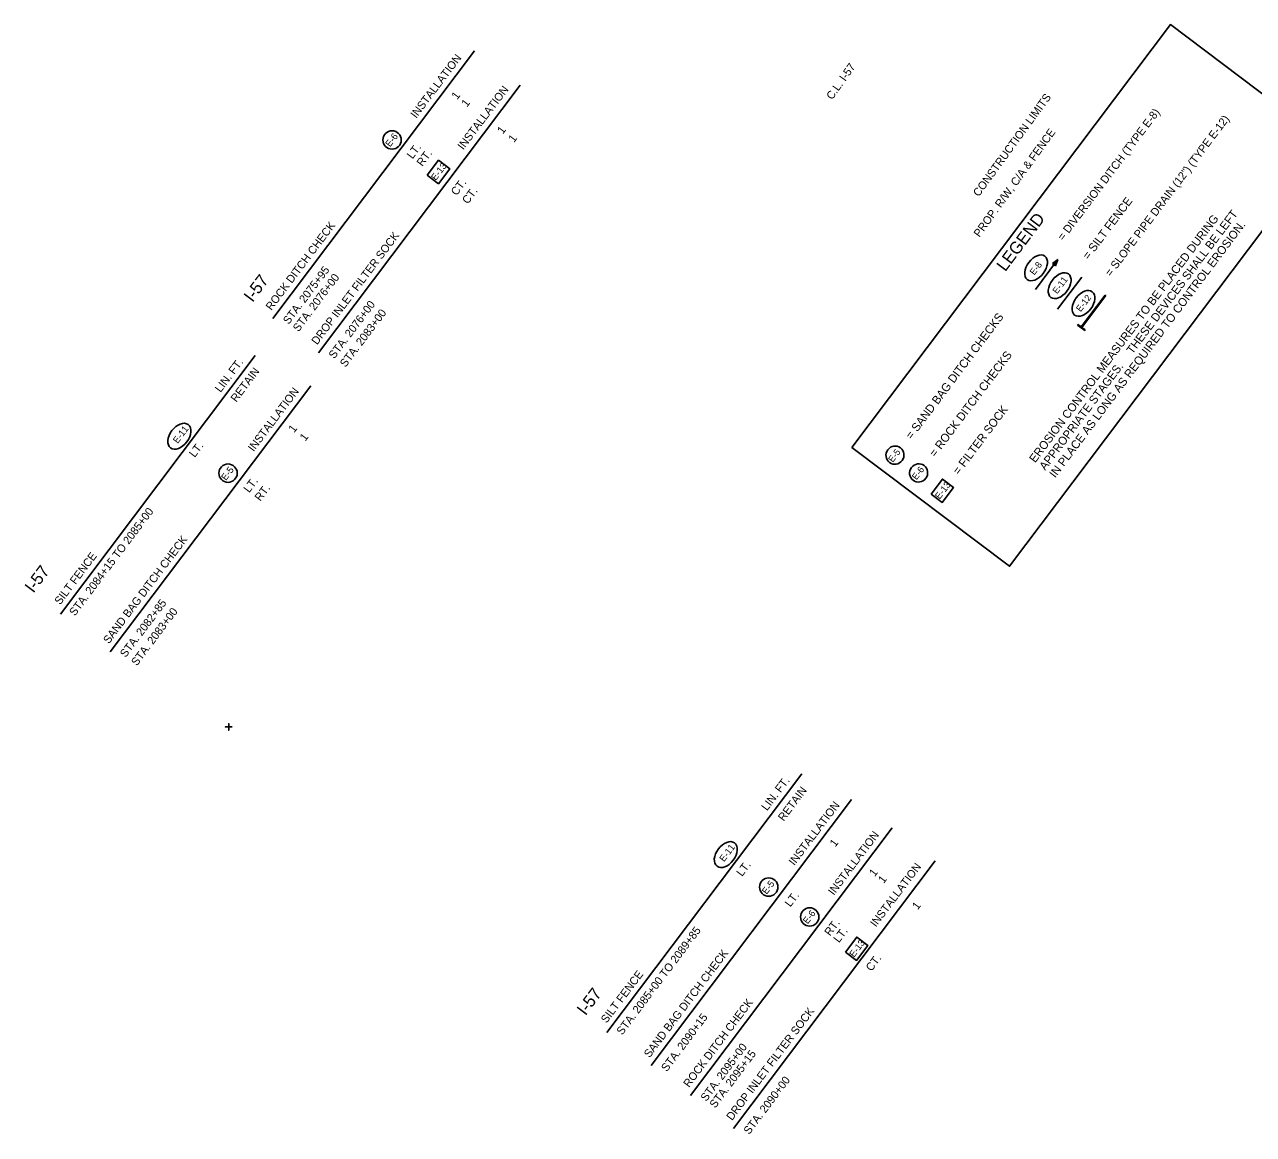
# Model space of a CAD drawing. Extents: x 1713742 to 1715480, y 763715 to 765350.
# Drawn here: x 1713742 to 1714663, y 763715 to 764547 of the extents above; entities that cross this region are included whole.
import ezdxf

# ---------------------------------------------------------------- set-up
doc = ezdxf.new("R2010")
doc.units = 0
for name, color, linetype in [('1', 7, 'Continuous'), ('44', 7, 'Continuous'), ('Level 1', 7, 'Continuous'), ('Level 44', 7, 'Continuous'), ('Plan Notes', 7, 'Continuous'), ('R_Draft', 7, 'Continuous')]:
    doc.layers.add(name, color=color, linetype=linetype)

msp = doc.modelspace()

# ---------------------------------------------------------------- linework, layer by layer
at = {"layer": '1'}
for points in [[(1714362.47, 764230.05), (1714601.19, 764546.83), (1714719.3, 764457.83), (1714480.58, 764141.04)], [(1714044.19, 764433.96), (1714052.63, 764445.16), (1714061.02, 764438.84), (1714052.58, 764427.64)], [(1714421.82, 764195.09), (1714430.26, 764206.3), (1714438.65, 764199.97), (1714430.21, 764188.77)], [(1714357.63, 763851.95), (1714366.07, 763863.15), (1714374.46, 763856.83), (1714366.02, 763845.63)]]:
    msp.add_lwpolyline(points, close=True, dxfattribs=at)
for centre in [(1714017.86, 764460.38), (1713894.88, 764210.74), (1714300.12, 763900.64), (1714330.82, 763878.22)]:
    msp.add_circle(centre, 6.88, dxfattribs=at)
for centre in [(1713858.43, 764238.38), (1714267.94, 763924.95)]:
    msp.add_ellipse(centre, major_axis=(6.59, 8.75), ratio=0.638788, dxfattribs=at)
at = {"layer": '44'}
for p, q in [((1713928.48, 764326.74), (1714079.55, 764527.21)), ((1713962.71, 764300.95), (1714113.78, 764501.42)), ((1713769.39, 764105.14), (1713915.33, 764298.81)), ((1713806.66, 764076.94), (1713956.83, 764276.22)), ((1714178.9, 763791.7), (1714324.84, 763985.37)), ((1714211.89, 763766.84), (1714362.06, 763966.12)), ((1714241.44, 763744.58), (1714392.51, 763945.05)), ((1714273.67, 763719.78), (1714424.74, 763920.25))]:
    msp.add_line(p, q, dxfattribs=at)
at = {"layer": 'Level 1'}
for p, q in [((1714516.89, 764370.87), (1714512.85, 764367.9)), ((1714512.85, 764367.9), (1714515.16, 764366.16)), ((1714515.92, 764370.04), (1714513.15, 764367.69)), ((1714515.98, 764369.98), (1714513.44, 764367.47)), ((1714516.05, 764369.91), (1714513.72, 764367.26)), ((1714514.3, 764366.81), (1714516.21, 764369.8)), ((1714514.58, 764366.6), (1714516.28, 764369.74)), ((1714514.87, 764366.38), (1714516.37, 764369.71)), ((1714515.16, 764366.16), (1714516.89, 764370.87))]:
    msp.add_line(p, q, dxfattribs=at)
msp.add_lwpolyline([(1714499.93, 764348.36), (1714515.88, 764369.52)], dxfattribs=at)
for centre, major_axis, ratio in [((1714500.46, 764364.55), (6.59, 8.75), 0.622952), ((1714518.18, 764351.22), (6.59, 8.76), 0.622952), ((1714535.99, 764337.97), (6.59, 8.75), 0.622952), ((1714394.73, 764224.24), (-4.14, -5.5), 0.97521), ((1714412.45, 764210.91), (-4.14, -5.5), 0.97521)]:
    msp.add_ellipse(centre, major_axis=major_axis, ratio=ratio, dxfattribs=at)
at = {"layer": 'Level 44'}
for p, q in [((1714552.3, 764344.13), (1714534.33, 764320.27)), ((1714552.7, 764343.83), (1714534.73, 764319.97)), ((1714552.3, 764344.13), (1714552.7, 764343.83)), ((1714531.54, 764321.74), (1714531.84, 764322.14)), ((1714536.91, 764317.7), (1714531.54, 764321.74)), ((1714534.33, 764320.27), (1714531.84, 764322.14)), ((1714537.21, 764318.1), (1714534.73, 764319.97)), ((1714536.91, 764317.7), (1714537.21, 764318.1))]:
    msp.add_line(p, q, dxfattribs=at)
msp.add_lwpolyline([(1714516.58, 764333.58), (1714534.68, 764357.66)], dxfattribs=at)
at = {"layer": 'Plan Notes'}
msp.add_lwpolyline([(1713895.44, 764020.61), (1713895.44, 764023.11), (1713895.44, 764020.61), (1713892.94, 764020.61), (1713895.44, 764020.61), (1713895.44, 764018.11), (1713895.44, 764020.61), (1713897.94, 764020.61)], dxfattribs=at)

# ---------------------------------------------------------------- texts
at = {"layer": '1'}
for s, rotation, p in [('E-6 ', 53, (1714016.34, 764454.74)), ('E-13', 52.61773, (1714050.59, 764429.64)), ('E-11', 53, (1713857.13, 764232.58)), ('E-5 ', 53, (1713893.31, 764204.87)), ('E-13', 52.61773, (1714428.22, 764190.78)), ('E-11', 53, (1714266.65, 763919.14)), ('E-5 ', 53, (1714298.54, 763894.78)), ('E-6 ', 53, (1714329.29, 763872.58)), ('E-13', 52.61773, (1714364.03, 763847.63))]:
    msp.add_text(s, height=4.999, rotation=rotation, dxfattribs=at).set_placement(p)
at = {"layer": '44'}
for s, p in [('INSTALLATION', (1714035.91, 764476.21)), ('1', (1714066.6, 764490.14)), ('INSTALLATION', (1714071.2, 764452.52)), ('1', (1714073.99, 764484.57)), ('1', (1714100.83, 764464.35)), ('LT.', (1714033.11, 764445.71)), ('1', (1714109.22, 764458.02)), ('RT.', (1714040.51, 764440.13)), ('CT.', (1714066.18, 764418.24)), ('CT.', (1714074.58, 764411.92)), ('ROCK DITCH CHECK', (1713927.4, 764332.22)), ('DROP INLET FILTER SOCK', (1713961.63, 764306.43)), ('STA. 2075+95', (1713940.33, 764321.77)), ('STA. 2075+95', (1713940.33, 764321.77)), ('STA. 2076+00', (1713947.72, 764316.2)), ('STA. 2076+00', (1713974.55, 764295.98)), ('STA. 2083+00', (1713982.95, 764289.65)), ('LIN. FT.', (1713889.31, 764270.78)), ('RETAIN', (1713901.13, 764263.49)), ('INSTALLATION', (1713914.09, 764226.41)), ('1', (1713944.43, 764240.6)), ('1', (1713944.43, 764240.6)), ('1', (1713952.83, 764234.27)), ('LT.', (1713869.93, 764222.08)), ('LT.', (1713910.73, 764195.62)), ('LT.', (1713910.73, 764195.62)), ('RT.', (1713919.12, 764189.29)), ('STA. 2084+15 TO 2085+00', (1713780.11, 764103.31)), ('SAND BAG DITCH CHECK', (1713805.58, 764082.42)), ('SILT FENCE      ', (1713769.07, 764111.63)), ('STA. 2082+85', (1713818.16, 764072.23)), ('STA. 2082+85', (1713818.16, 764072.23)), ('STA. 2083+00', (1713826.55, 764065.91)), ('LIN. FT.', (1714298.82, 763957.34)), ('RETAIN', (1714311.33, 763949.55)), ('INSTALLATION', (1714319.32, 763916.32)), ('INSTALLATION', (1714348.87, 763894.05)), ('1', (1714350.01, 763930.24)), ('1', (1714350.01, 763930.24)), ('LT.', (1714280.13, 763908.14)), ('1', (1714379.56, 763907.98)), ('INSTALLATION', (1714380.43, 763870.27)), ('1', (1714386.28, 763902.91)), ('LT.', (1714316.31, 763885.26)), ('LT.', (1714316.31, 763885.26)), ('1', (1714411.79, 763883.18)), ('STA. 2085+00 TO 2089+85', (1714190.31, 763789.36)), ('STA. 2085+00 TO 2089+85', (1714190.31, 763789.36)), ('RT.', (1714346.07, 763863.54)), ('LT.', (1714352.79, 763858.48)), ('SAND BAG DITCH CHECK', (1714210.82, 763772.33)), ('CT.', (1714377.14, 763837.08)), ('SILT FENCE      ', (1714178.58, 763798.2)), ('ROCK DITCH CHECK', (1714240.36, 763750.06)), ('STA. 2090+15', (1714223.74, 763761.88)), ('STA. 2090+15', (1714223.74, 763761.88)), ('DROP INLET FILTER SOCK', (1714272.59, 763725.27)), ('STA. 2095+00', (1714253.28, 763739.61)), ('STA. 2095+15', (1714260, 763734.55)), ('STA. 2095+15', (1714260, 763734.55)), ('STA. 2090+00', (1714285.51, 763714.82))]:
    msp.add_text(s, height=6, rotation=53, dxfattribs=at).set_placement(p)
at = {"layer": 'Level 1'}
for s, height, rotation, p in [('= DIVERSION DITCH (TYPE E-8)', 6, 53.00001, (1714520.78, 764384.46)), ('= SLOPE PIPE DRAIN (12") (TYPE E-12)', 6, 53.00001, (1714556.42, 764357.61)), ('= SILT FENCE', 6.25, 53.058, (1714539.7, 764370.22)), ('EROSION CONTROL MEASURES TO BE PLACED DURING', 6.25, 53.058, (1714499.8, 764218.1)), ('THESE DEVICES SHALL BE LEFT', 6.25, 53.058, (1714572.75, 764299.45)), ('IN PLACE AS LONG AS REQUIRED TO CONTROL EROSION.', 6.25, 53.058, (1714514.85, 764206.79)), ('E-8', 4.876, 53.00001, (1714499.15, 764358.76)), ('E-11 ', 4.876, 53.058, (1714516.25, 764344.67)), ('E-12', 4.876, 53.00001, (1714533.9, 764331.19)), ('= SAND BAG DITCH CHECKS', 6.25, 53.058, (1714407.16, 764235.57)), ('= ROCK DITCH CHECKS', 6.25, 53.058, (1714424.88, 764222.25)), ('APPROPRIATE STAGES. ', 6.25, 53.058, (1714507.32, 764212.45)), ('= FILTER SOCK', 6.25, 53.00001, (1714442.49, 764208.97)), ('E-5 ', 4.876, 53.058, (1714393.11, 764218.4)), ('E-6 ', 4.876, 53.058, (1714410.89, 764205.3))]:
    msp.add_text(s, height=height, rotation=rotation, dxfattribs=at).set_placement(p)
at = {"layer": 'Level 44'}
for s, rotation, p in [('LEGEND', 53.058, (1714477.4, 764361.24)), ('I-57', 53.00001, (1713913.22, 764338.24)), ('I-57', 53.00001, (1713749.04, 764120.36)), ('I-57', 53.00001, (1714162.84, 763803.81))]:
    msp.add_text(s, height=9.143, rotation=rotation, dxfattribs=at).set_placement(p)
at = {"layer": 'R_Draft'}
for s, rotation, p in [('C.L. I-57', 54.64067, (1714347.64, 764490.06)), ('CONSTRUCTION LIMITS', 53.95469, (1714457.54, 764417.45)), ('PROP. R/W, C/A & FENCE', 54.05542, (1714458.01, 764387.07))]:
    msp.add_text(s, height=6, rotation=rotation, dxfattribs=at).set_placement(p)

doc.saveas('drawing.dxf')
